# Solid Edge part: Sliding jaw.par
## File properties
Title: Sliding Jaw
Author: Abhinav Rai
Template: Normal.par
Last saved by: Cadcim
Revision: 18
Application: Solid Edge
Density: 0.0000078 kg/mm^3
Accuracy: 0.01
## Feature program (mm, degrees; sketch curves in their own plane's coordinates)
sketch used by "unnamed Protrusion 1" plane through (0, 0, 0) normal (0, -1, 0) x-axis (1, 0, 0)
  line (-34.0632, 44.45) -> (-34.0632, 0)
  line (-34.0632, 0) -> (5.6116, 0)
  line (5.6116, 0) -> (5.6116, 19.9608)
  line (-34.0632, 44.45) -> (-19.6102, 44.45)
  arc centre (-37.2382, 14.3002) radius 34.925 from (-19.6102, 44.45) to (-3.8245, 24.463) cw
  arc centre (2.2507, 26.3108) radius 6.35 from (-3.8245, 24.463) to (2.2507, 19.9608) ccw
  line (5.6116, 19.9608) -> (2.2507, 19.9608)
  dimension (linear) = 37.2382
extrude "unnamed Protrusion 1" add finite 69.7992 symmetric
sketch for "ExtrudedProtrusion_2" plane through (5.6116, 0, 9.9804) normal (1, 0, 0) x-axis (0, 1, 0)
extrude "ExtrudedProtrusion_2" add finite 65.0748 along -normal
sketch for "unnamed Cutout 1" plane through (-26.9258, -15.24, -27.8638) normal (0, -1, 0) x-axis (1, 0, 0)
extrude "unnamed Cutout 1" cut through along -normal
sketch for "unnamed Protrusion 2" plane through (5.6116, 0, -9.0696) normal (1, 0, 0) x-axis (0, 1, 0)
  arc centre (0, 26.5956) radius 23.9515 from (-23.8274, 29.0304) to (23.8274, 29.0304) cw
  line (-23.8274, 29.0304) -> (23.8274, 29.0304)
extrude "unnamed Protrusion 2" add through along -normal
sketch for "Hole_1" plane through (5.6116, 0, -0.1583) normal (1, 0, 0) x-axis (0, 1, 0)
hole "Hole_1" diameter 19.05 through
fillet "Round_1" radius 3.175
sketch for "Hole_2" plane through (-26.9258, 0, -38.1) normal (0, 0, -1) x-axis (0, 1, 0)
  hole centre (7.9375, 2.3876) bore radius 2.7686
hole "Hole_2" diameter 5.5372 finite
sketch for "unnamed Hole 1" plane through (-26.9258, 0, -38.1) normal (0, 0, -1) x-axis (0, 1, 0)
  hole centre (-7.9375, 2.3876) bore radius 2.7686
hole "unnamed Hole 1" finite
sketch for "Hole_4" plane through (-34.0632, 0, 22.225) normal (-1, 0, 0) x-axis (0, -1, 0)
  hole centre (19.0754, 3.175) bore radius 3.175
hole "Hole_4" diameter 6.35 finite
sketch for "unnamed Hole 2" plane through (-34.0632, 0, 22.225) normal (-1, 0, 0) x-axis (0, -1, 0)
  hole centre (-19.0246, 3.175) bore radius 3.175
  dimension (linear) = 19.0246
hole "unnamed Hole 2" finite
pattern "unnamed Pattern 1" of "Hole_2", "unnamed Hole 1"
pattern "unnamed Pattern 2" of "Hole_4", "unnamed Hole 2"
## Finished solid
Body 1: solid body, 48 faces, 109 edges, 62 vertices.
  Faces by surface: plane 26, cylinder 16, torus 4, sphere 2
  Edges by curve: line 69, circle 33, intersection 7
Bounding box of the edges (mm; curved faces can reach further): 65.075 x 69.799 x 82.550, from (-59.4632, -34.8996, -38.1) to (5.6116, 34.8996, 44.45).
Cylindrical faces by radius (mm): R2.7686 x2, R3.1242 x1, R3.175 x8, R6.35 x2, R9.525 x1, R23.9515 x1, R34.925 x1
Toroidal faces (ring radius, tube radius in mm): R9.525 r3.175 x2, R31.75 r3.175 x2
Spherical faces by radius (mm): R3.175 x2
Planar faces by outward normal: +x 1, +y 4, +z 6, -x 3, -y 4, -z 7, oblique 1
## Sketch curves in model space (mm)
line (-34.0632, 0, 0) -> (5.6116, 0, 0)
line (5.6116, 0, 0) -> (5.6116, 0, 19.9608)
line (5.6116, 0, 19.9608) -> (2.2507, 0, 19.9608)
arc centre (2.2507, 0, 26.3108) radius 6.35 from (-3.8245, 0, 24.463) through (-1.5301, 0, 21.209) to (2.2507, 0, 19.9608)
arc centre (-37.2382, 0, 14.3002) radius 34.925 from (-19.6102, 0, 44.45) through (-9.8305, 0, 35.9468) to (-3.8245, 0, 24.463)
line (-34.0632, 0, 44.45) -> (-19.6102, 0, 44.45)
line (-34.0632, 0, 44.45) -> (-34.0632, 0, 0)
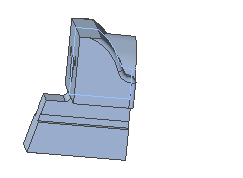
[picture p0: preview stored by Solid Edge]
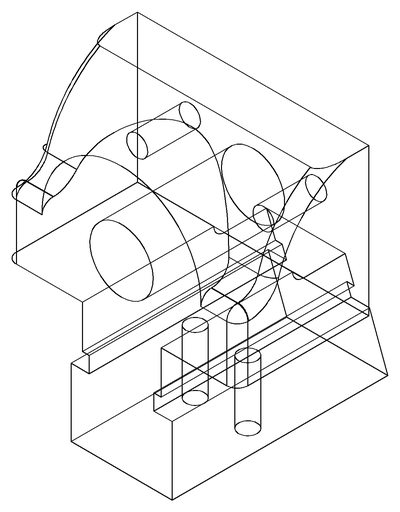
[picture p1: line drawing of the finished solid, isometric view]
